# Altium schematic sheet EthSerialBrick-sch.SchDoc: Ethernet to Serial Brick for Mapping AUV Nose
size Tabloid; Organization: Monterey Bay Aquarium Research Institute; Address1: 7700 Sandholdt Rd; Address2: Moss Landing, CA 95039-9644; DocumentNumber: 1002305; Revision: 2; SheetNumber: 1; SheetTotal: 1; CompanyName: MBARI; Engineer: Mark Sibenac
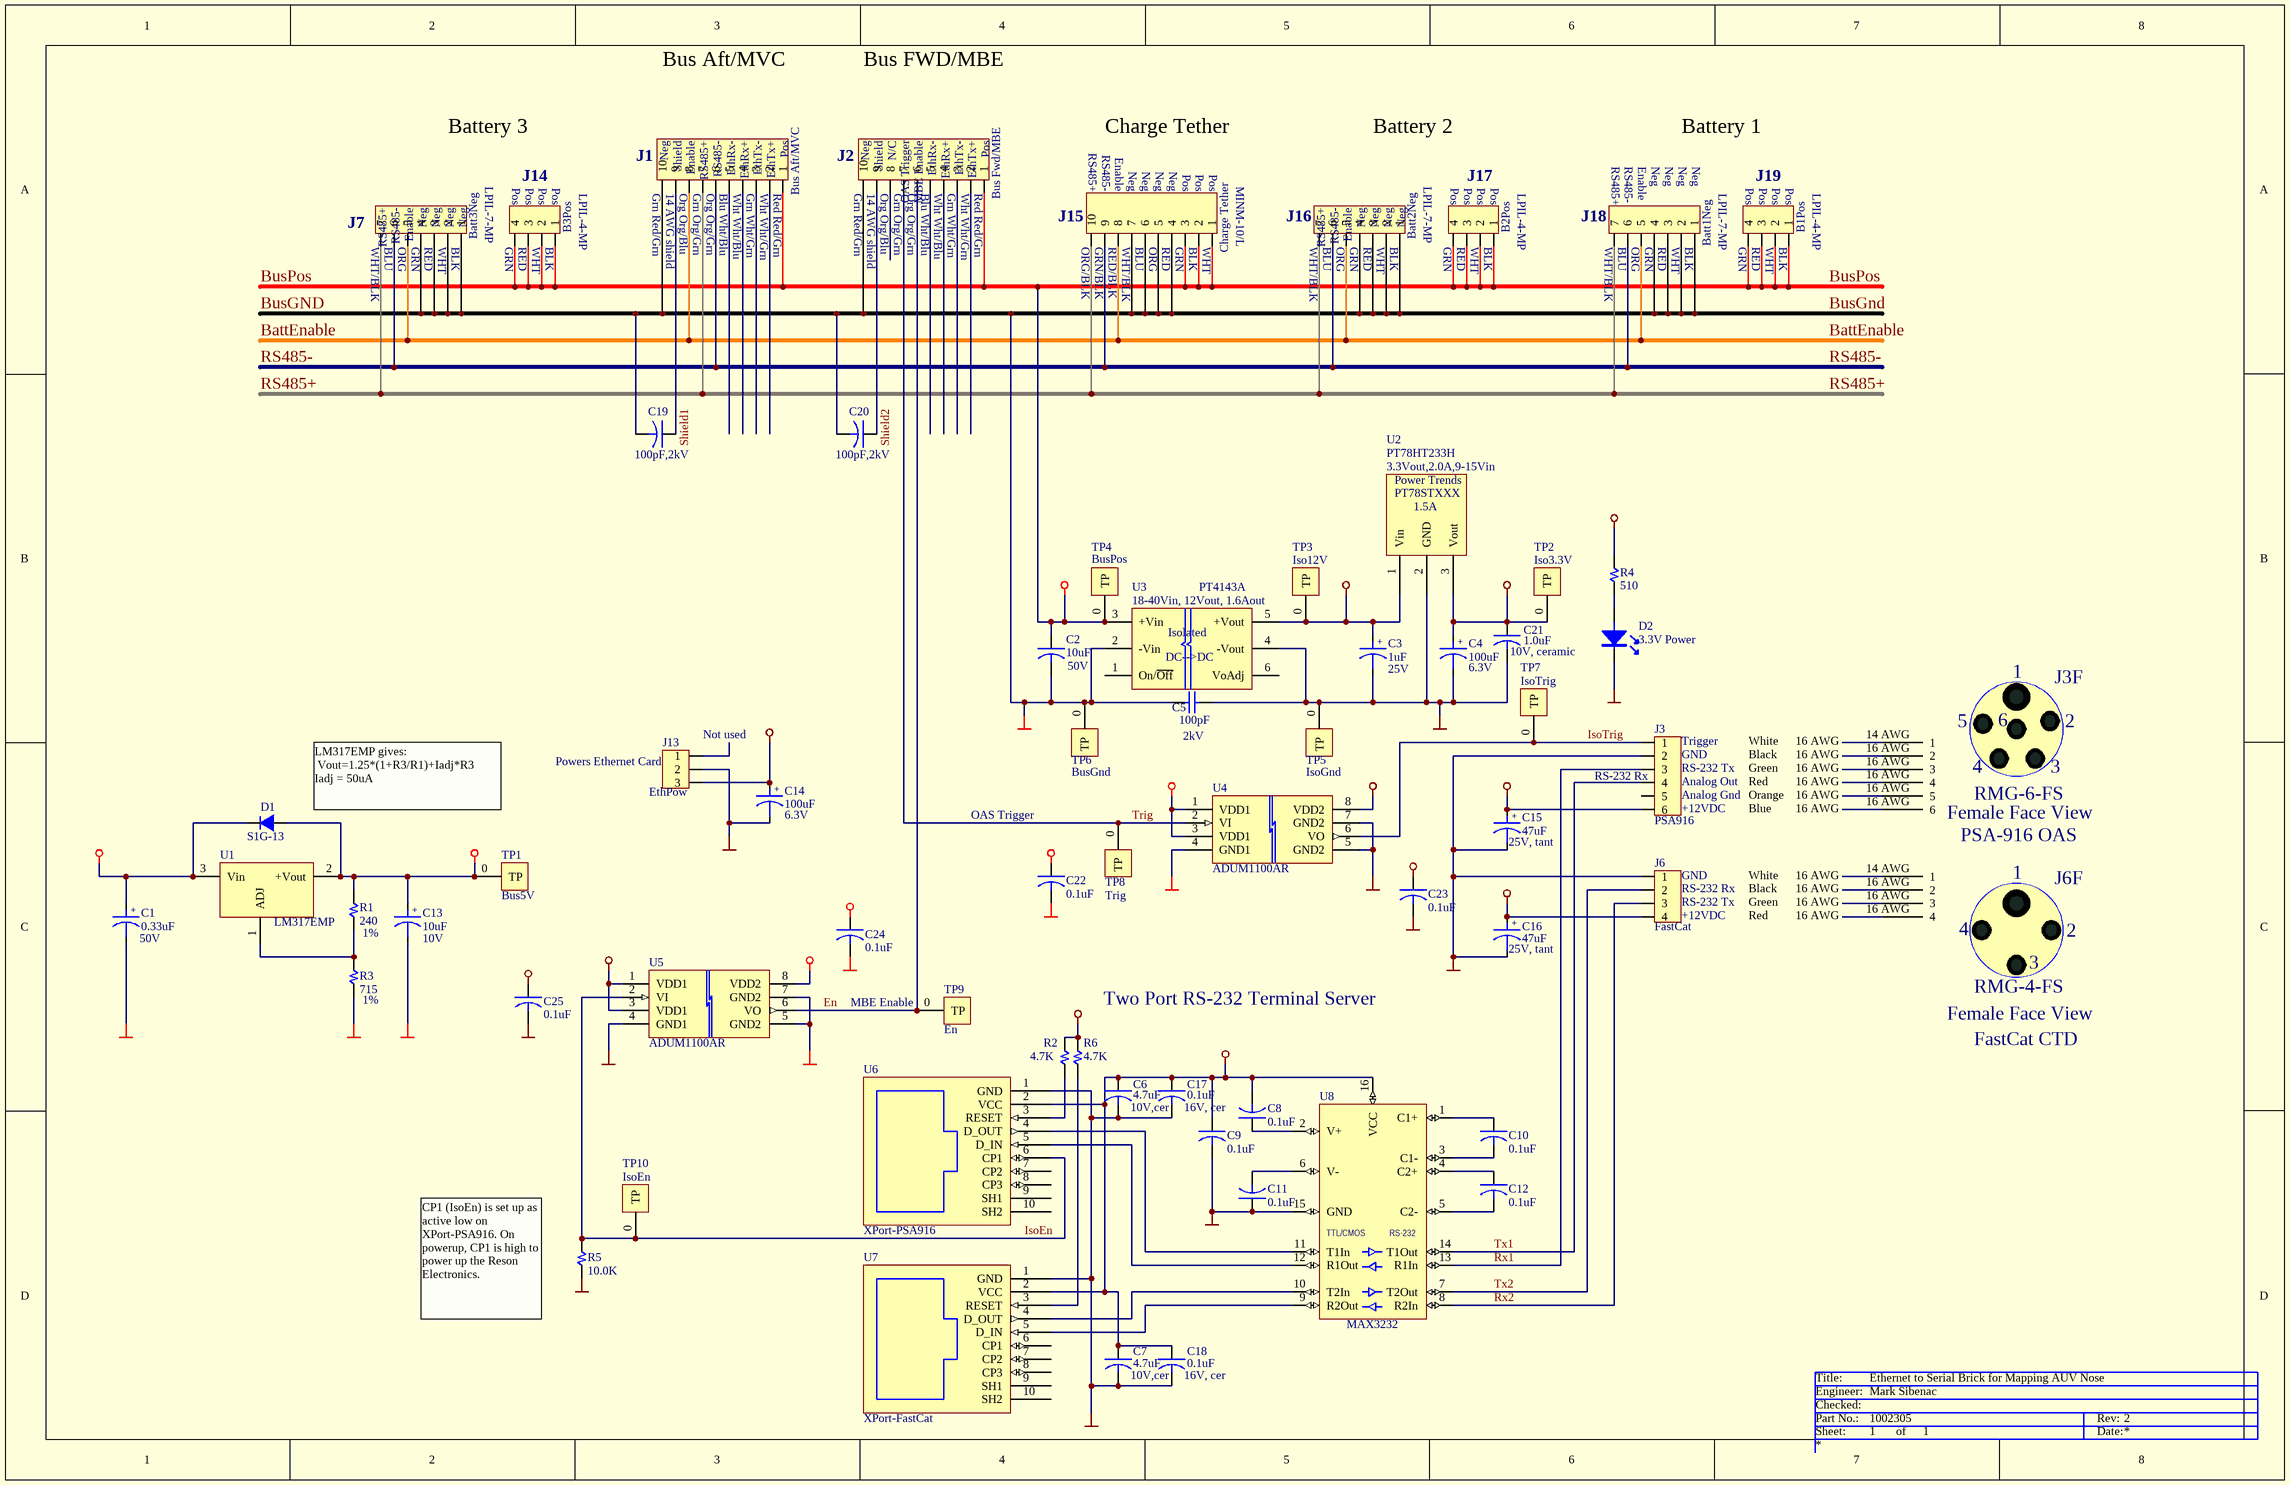
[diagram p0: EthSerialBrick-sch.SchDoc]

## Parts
C1  0.33uF  DescSheet: 50V  [3528POL]
C2  10uF  DescSheet: 50V  [CAPSTICK-CS4-5]
C3  1uF  DescSheet: 25V  [3216POL]
C4  100uF  DescSheet: 6.3V  [3528POL]
C5  100pF  DescSheet: 2kV  [ECK]
C6  4.7uF  DescSheet: 10V,cer  [1206]
C7  4.7uF  DescSheet: 10V,cer  [1206]
C8  0.1uF  [1206]
C9  0.1uF  [1206]
C10  0.1uF  [1206]
C11  0.1uF  [1206]
C12  0.1uF  [1206]
C13  10uF  DescSheet: 10V  [3216POL]
C14  100uF  DescSheet: 6.3V  [3528POL]
C15  47uF  DescSheet: 25V, tant  [7343pol]
C16  47uF  DescSheet: 25V, tant  [7343pol]
C17  0.1uF  DescSheet: 16V, cer  [1206]
C18  0.1uF  DescSheet: 16V, cer  [1206]
C19  100pF,2kV  [ECK]
C20  100pF,2kV  [ECK]
C21  1.0uF  DescSheet: 10V, ceramic  [1206]
C22  0.1uF  [1206]
C23  0.1uF  [1206]
C24  0.1uF  [1206]
C25  0.1uF  [1206]
D1  S1G-13  [SMA]
D2  3.3V Power  [SOT-23]
J1  Bus Aft/MVC  [MINK-10-SOLDERPADS]
J2  Bus Fwd/MBE  [MINK-10-SOLDERPADS]
J3  PSA916  [SIP6]
J3F  RMG-6-FS  DescSheet: PSA-916 OAS  (mechanical)
J6  FastCat  [SIP4]
J6F  RMG-4-FS  DescSheet: FastCat CTD  (mechanical)
J7  Batt3Neg  [LPIL-7-SOLDERPADS]
J13  EthPow  [SIP3]
J14  B3Pos  [LPIL-4-SOLDERPADS]
J15  Charge Tether  [MINM-10-SOLDERPADS]
J16  Batt2Neg  [LPIL-7-SOLDERPADS]
J17  B2Pos  [LPIL-4-SOLDERPADS]
J18  Batt1Neg  [LPIL-7-SOLDERPADS]
J19  B1Pos  [LPIL-4-SOLDERPADS]
R1  240  DescSheet: 1%  [1206]
R2  4.7K  [1206]
R3  715  DescSheet: 1%  [1206]
R4  510  [1206]
R5  10.0K  [1206]
R6  4.7K  [1206]
TP1  Bus5V  [TP-PAD-35]
TP2  Iso3.3V  [TP-PAD-35]
TP3  Iso12V  [TP-PAD-35]
TP4  BusPos  [TP-PAD-35]
TP5  IsoGnd  [TP-PAD-35]
TP6  BusGnd  [TP-PAD-35]
TP7  IsoTrig  [TP-PAD-35]
TP8  Trig  [TP-PAD-35]
TP9  En  [TP-PAD-35]
TP10  IsoEn  [TP-PAD-35]
U1  LM317EMP  [SOT-223]
U2  PT78HT233H  DescSheet: 3.3Vout,2.0A,9-15Vin  [PT78ST-HORIZ]
U3  PT4143A  DescSheet: 18-40Vin, 12Vout, 1.6Aout  [TI-EGD]
U4  ADUM1100AR  [SO-G8/D5]
U5  ADUM1100AR  [SO-G8/D5]
U6  XPort-PSA916  [XPORT]
U7  XPort-FastCat  [XPORT]
U8  MAX3232  [SOIC-16-0.15W]

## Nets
Bus5V: C13.1 C22.1 C24.1 D1.1(K) R1.1 TP1.0(TP) U1.2(+Vout) U1.4(+Vout) U4.1(VDD1) U4.3(VDD1) U5.8(VDD2)
BusGND: C1.2 C2.2 C5.1 C13.2 C19.2 C20.2 C22.2 C24.2 J1.10 J2.10 J7.1 J7.2 J7.3 J7.4 J15.4 J15.5 J15.6 J15.7 J16.1 J16.2 J16.3 J16.4 J18.1 J18.2 J18.3 J18.4 R3.1 TP6.0(TP) U3.2(-Vin) U4.4(GND1) U5.5(GND2) U5.7(GND2)
BusPos: C1.1 C2.1 D1.2(A) J1.1 J2.1 J14.1 J14.2 J14.3 J14.4 J15.1 J15.2 J15.3 J17.1 J17.2 J17.3 J17.4 J19.1 J19.2 J19.3 J19.4 TP4.0(TP) U1.3(Vin) U3.3(+Vin)
Iso3.3V: C4.1 C6.1 C7.1 C8.2 C9.1 C14.1 C17.1 C18.1 C21.1 C23.1 C25.1 J13.3 R2.2 R4.1 R6.2 TP2.0(TP) U2.3(Vout) U4.8(VDD2) U5.1(VDD1) U5.3(VDD1) U6.2(VCC) U7.2(VCC) U8.16(VCC)
Iso12V: C3.1 C15.1 C16.1 J3.6 J6.4 TP3.0(TP) U2.1(Vin) U3.5(+Vout)
IsoGND: C3.2 C4.2 C5.2 C6.2 C7.2 C9.2 C11.1 C14.2 C15.2 C16.2 C17.2 C18.2 C21.2 C23.2 C25.2 D2.3(K) J3.2 J6.1 J13.2 R5.1 TP5.0(TP) U2.2(GND) U3.4(-Vout) U4.5(GND2) U4.7(GND2) U5.4(GND1) U6.1(GND) U7.1(GND) U8.15(GND)
BattEnable: J1.8 J7.5 J15.8 J16.5 J18.5
En: J2.6 TP9.0(TP) U5.6(VO)
IsoEn: R5.2 TP10.0(TP) U5.2(VI) U6.6(CP1)
IsoTrig: J3.1 TP7.0(TP) U4.6(VO)
RS485+: J1.7 J7.7 J15.10 J16.7 J18.7
RS485-: J1.6 J7.6 J15.9 J16.6 J18.6
Rx1: J3.3 U8.13(R1In)
Rx2: J6.3 U8.8(R2In)
Shield1: C19.1 J1.9
Shield2: C20.1 J2.9
Trig: J2.7 TP8.0(TP) U4.2(VI)
Tx1: J3.4 U8.14(T1Out)
Tx2: J6.2 U8.7(T2Out)
NetC8_1: C8.1 U8.2(V+)
NetC10_1: C10.1 U8.1(C1+)
NetC10_2: C10.2 U8.3(C1-)
NetC11_2: C11.2 U8.6(V-)
NetC12_1: C12.1 U8.4(C2+)
NetC12_2: C12.2 U8.5(C2-)
NetD2_2: D2.2(A) R4.2
NetR1_2: R1.2 R3.2 U1.1(ADJ)
NetR2_1: R2.1 U6.3(RESET)
NetR6_1: R6.1 U7.3(RESET)
NetU6_4: U6.4(D_OUT) U8.11(T1In)
NetU6_5: U6.5(D_IN) U8.12(R1Out)
NetU7_4: U7.4(D_OUT) U8.10(T2In)
NetU7_5: U7.5(D_IN) U8.9(R2Out)

Not connected (* = marked no-connect by the designer): J1 2 3 4 5; J2 2 3 4 5 8; J3 5; J3F 14 AWG(1) 16 AWG(2); J6F 14 AWG(1) 16 AWG(2); J13 1; U3 1(On/~{Off}) 6(VoAdj); U6 7(CP2) 8(CP3) 9(SH1) 10(SH2); U7 6(CP1) 7(CP2) 8(CP3) 9(SH1) 10(SH2)

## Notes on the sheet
- Bus Aft/MVC
- Bus FWD/MBE
- Battery 3
- (near J1) Neg
- (near J1) Shield
- (near J1) Enable
- (near J1) RS485+
- (near J1) RS485-
- (near J1) EthRx-
- (near J1) EthRx+
- (near J1) EthTx-
- (near J1) EthTx+
- (near J1) Pos
- (near J2) Neg
- (near J2) Shield
- (near J2) N/C
- (near J2) OAS Trigger
- (near J2) MBE Enable
- (near J2) EthRx-
- (near J2) EthRx+
- (near J2) EthTx-
- (near J2) EthTx+
- (near J2) Pos
- (near J15) RS485+
- Charge Tether
- Battery 2
- (near J18) RS485+
- (near J18) RS485-
- (near J18) Enable
- (near J18) Neg
- Battery 1
- Neg
- (near J7) RS485+
- (near J7) RS485-
- (near J7) Enable
- (near J7) Neg
- LPIL-7-MP
- (near J14) Pos
- (near J14) LPIL-4-MP
- (near J1) Grn Red/Grn
- (near J1) 14 AWG shield
- (near J1) Org Org/Blu
- (near J1) Grn Org/Grn
- (near J1) Org Org/Grn
- (near J1) Blu Wht/Blu
- (near J1) Wht Wht/Blu
- (near J1) Grn Wht/Grn
- (near J1) Wht Wht/Grn
- (near J1) Red Red/Grn
- (near J2) Grn Red/Grn
- (near J2) 14 AWG shield
- (near J2) Org Org/Blu
- (near J2) Grn Org/Grn
- (near J2) Org Org/Grn
- (near J2) Blu Wht/Blu
- (near J2) Wht Wht/Blu
- (near J2) Grn Wht/Grn
- (near J2) Wht Wht/Grn
- (near J2) Red Red/Grn
- (near J15) RS485-
- (near J15) Enable
- (near J15) Neg
- (near J15) Pos
- (near J15) MINM-10/L
- (near J16) RS485+
- (near J16) RS485-
- (near J16) Enable
- (near J16) Neg
- (near J17) Pos
- (near J17) LPIL-4-MP
- (near J19) Pos
- (near J19) LPIL-4-MP
- (near J7) WHT/BLK
- (near J7) BLU
- (near J7) ORG
- (near J7) GRN
- (near J7) RED
- (near J7) WHT
- (near J7) BLK
- (near J14) GRN
- (near J14) RED
- (near J14) WHT
- (near J14) BLK
- (near J15) ORG/BLK
- (near J15) GRN/BLK
- (near J15) RED/BLK
- (near J15) WHT/BLK
- (near J15) BLU
- (near J15) ORG
- (near J15) RED
- (near J15) GRN
- (near J15) BLK
- (near J15) WHT
- (near J16) WHT/BLK
- (near J16) BLU
- (near J16) ORG
- (near J16) GRN
- (near J16) RED
- (near J16) WHT
- (near J16) BLK
- (near J17) GRN
- (near J17) RED
- (near J17) WHT
- (near J17) BLK
- (near J18) WHT/BLK
- (near J18) BLU
- (near J18) ORG
- (near J18) GRN
- (near J18) RED
- (near J18) WHT
- (near J18) BLK
- (near J19) GRN
- (near J19) RED
- (near J19) WHT
- (near J19) BLK
- (near J13) Powers Ethernet Card
- (near J13) Not used
- (near J3) GND
- (near J3) Trigger
- Black
- White
- 16 AWG
- LM317EMP gives:
  Vout=1.25*(1+R3/R1)+Iadj*R3
  Iadj = 50uA
- OAS Trigger
- (near J3) RS-232 Rx
- (near J3) RS-232 Tx
- (near J3) +12VDC
- (near J3) Analog Out
- (near J3) Analog Gnd
- Orange
- Blue
- Red
- Green
- (near J6) GND
- (near J6) RS-232 Rx
- (near J6) RS-232 Tx
- (near J6) +12VDC
- MBE Enable
- Two Port RS-232 Terminal Server
- (near R5) CP1 (IsoEn) is set up as active low on XPort-PSA916. On powerup, CP1 is high to power up the Reson Electronics.

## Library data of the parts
C1 = CAPACITOR POL: Capacitor; ManufPartNo: T491B334M050AS; Manufacturer: Kemet; VendorPartNo: 399-1659-1-ND; Cost/ea: 0.30; Reference: T041, 773; Vendor: Digi-Key
C2 = CAPACITOR: ManufPartNo: 106K050CS4; Manufacturer: ITW Paktron; Cost/ea: 13.92; Vendor: Future
C3 = CAPACITOR POL: Capacitor; ManufPartNo: T491A105K025AS; Manufacturer: Kemet; VendorPartNo: 399-1624-1-ND; Cost/ea: 0.19; Reference: T041, 773; Vendor: Digi-Key
C4 C14 = CAPACITOR POL: Capacitor; ManufPartNo: T491B107M006AS; Manufacturer: Kemet; VendorPartNo: 399-3195-1-ND; Cost/ea: 0.93; Reference: T041, 772; Vendor: Digi-Key
C5 = Cap: Capacitor; Manufacturer: Panasonic; ManufPartNo: ECK-T3D101KB; VendorPartNo: PCC2092CT-ND; Cost/ea: 0.99; Reference: T041, 813; Vendor: Digi-Key
C6 C7 = CAPACITOR: ManufPartNo: ECJ-3YB1A475K; Manufacturer: Panasonic; VendorPartNo: PCC2295CT-ND; Cost/ea: 0.513; Reference: T041, 822; Vendor: Digi-Key
C8-C12 C22-C25 = CAPACITOR: ManufPartNo: ECJ-3VB1C104K; Manufacturer: Panasonic; VendorPartNo: PCC1870CT-ND; Cost/ea: 0.183; DescSheet: 16V, cer; Reference: T041, 822; Vendor: Digi-Key
C13 = CAPACITOR POL: Capacitor; ManufPartNo: T491A106K010AS; Manufacturer: Panasonic; VendorPartNo: 399-1563-1-ND; Cost/ea: 0.20; Reference: T041, 772; Vendor: Digi-Key
C15 C16 = CAPACITOR POL: Capacitor; ManufPartNo: T491D476M025AS; Manufacturer: Kemet; VendorPartNo: 399-3210-1-ND; Cost/ea: 1.16; Reference: T041, 773; Vendor: Digi-Key
C17 C18 = CAPACITOR: ManufPartNo: ECJ-3VB1C104K; Manufacturer: Panasonic; VendorPartNo: PCC1870CT-ND; Cost/ea: 0.183; Reference: T041, 822; Vendor: Digi-Key
C19 C20 = CAPACITOR: ManufPartNo: ECK-T3D101KB; Manufacturer: Panasonic; VendorPartNo: PCC2092CT-ND; Cost/ea: 0.99; Reference: T041, 813; Vendor: Digi-Key
C21 = CAPACITOR: ManufPartNo: C1206C105K4RACTU; Manufacturer: Kemet; VendorPartNo: 399-1254-1-ND; Cost/ea: 0.33; Reference: T033, 785; Vendor: Digi-Key
D1 = DIODE_S: Diode; Manufacturer: Diodes Inc; VendorPartNo: S1GDICT-ND; Cost/ea: 0.288; DescSheet: 1A, 400V; Reference: T033, 578; Vendor: Digi-Key
D2 = LED: ManufPartNo: SML-LX15USBC-TR; Manufacturer: Lumex; VendorPartNo: 67-1668-1-ND; Cost/ea: 3.13; DescSheet: Ultra Blue; Reference: T032, 1138; Vendor: Digi-Key
J1 J2 J15 = CON10: Connector
J3 = CON6: Connector
J3F = IMPULSE-RMG-6-FS: Impulse RMG Connector
J6 J14 J17 = CON4: Connector
J6F = IMPULSE-RMG-4-FS: Impulse RMG Connector
J7 J16 J18 = CON7: Connector
J13 = CON3: Connector; ManufPartNo: PZC36SAEN; Manufacturer: Sullins; VendorPartNo: S1051-36-ND; Cost/ea: 2.62; Reference: T041, 93; Vendor: Digi-Key
J19 = CON4: Connector; Vendor: Subconn
R1 = RESISTOR: ManufPartNo: 9C12063A2400FKHFT; Manufacturer: Yaego; VendorPartNo: 311-240FCT-ND; Cost/ea: 0.088; Reference: T041, 861; Vendor: Digi-Key
R2 R6 = RESISTOR: ManufPartNo: 9C12063A4701FKHFT; Manufacturer: Yaego; VendorPartNo: 311-4.70KFCT-ND; Cost/ea: 0.088; Reference: T041, 861; Vendor: Digi-Key
R3 = RESISTOR: ManufPartNo: 9C12063A7150FKHFT; Manufacturer: Yaego; VendorPartNo: 311-715FCT-ND; Cost/ea: 0.088; Reference: T041, 861; Vendor: Digi-Key
R4 = RESISTOR: ManufPartNo: 9C12063A5100FKHFT; Manufacturer: Yageo; VendorPartNo: 311-510FCT-ND; Cost/ea: 0.088; Reference: T041, 861; Vendor: Digi-Key
R5 = RESISTOR: ManufPartNo: 9C12063A1002FKHFT; Manufacturer: Yageo; VendorPartNo: 311-10.0KFCT-ND; Cost/ea: 0.088; Reference: T041, 861; Vendor: Digi-Key
TP1-TP4 = TP PIN: Pad Pin for testpoints; ManufPartNo: 5000; Manufacturer: Keystone; VendorPartNo: 5000K-ND; Cost/ea: 0.023; DescSheet: Red; Reference: T041, 1082; Vendor: Digi-Key
TP5 TP6 = TP PIN: Pad Pin for testpoints; ManufPartNo: 5001; Manufacturer: Keystone; VendorPartNo: 5001K-ND; Cost/ea: 0.023; DescSheet: Black; Reference: T041, 1082; Vendor: Digi-Key
TP7-TP10 = TP PIN: Pad Pin for testpoints; ManufPartNo: 5002; Manufacturer: Keystone; VendorPartNo: 5002K-ND; Cost/ea: 0.023; DescSheet: White; Reference: T041, 1082; Vendor: Digi-Key
U1 = LM317: Regulator; Manufacturer: National Semiconductor; VendorPartNo: LM317EMPCT-ND; Cost/ea: 1.13; DescSheet: 1A; Reference: T041, 457; Vendor: Digi-Key
U2 = PT78STXXX: Power Trends Switching Reg; Manufacturer: TI Powertrends; VendorPartNo: PT78HT233H-ND; Cost/ea: 16.20; Reference: T041, 1170; Vendor: Digi-Key
U3 = PT4140-DC-DC: TI Isol DC->DC Converter; Manufacturer: TI Powertrends; VendorPartNo: PT4143-ND; Cost/ea: 46.23; Reference: T041, 1169; Vendor: Digi-Key
U4 U5 = ADUM1100AR: Digital Isolator; Manufacturer: Analog Devices; Cost/ea: 4.19; Vendor: Arrow Electronics
U6 U7 = XPORT: Serial to Ethernet Converter; Manufacturer: Lantronix; Cost/ea: 50.00; Vendor: Mouser
U8 = MAX232: MAX232 Communications Chip; ManufPartNo: MAX3232CSE; Manufacturer: Maxim; VendorPartNo: MAX3232CSE-ND; Cost/ea: 4.19; Reference: T041, 507; Vendor: Digi-Key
